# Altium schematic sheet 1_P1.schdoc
size 307 x 218 mm; Symbol: Drawing-Symbol_A4; Device: Drawing-Symbol_A4; Company: 嘉立创EDA; Version: V1.0; Page Size: A4; @Project Name: HDMI2CSI; @Page Count: 1; @Update Date: 2025-08-23; @Create Date: 2025-08-11; @Schematic Name: HDMI2CSI2; @Page No: 1; @Page Name: P1; @Create Time: 10:16:40; @Update Time: 00:30:52; Width: 1170; Height: 825; Region Start: 1; X Region Count: 6; Y Region Count: 4; Blade Width: 10; Title Block Position: 3; @Board Name: HDMI_2_CSI2
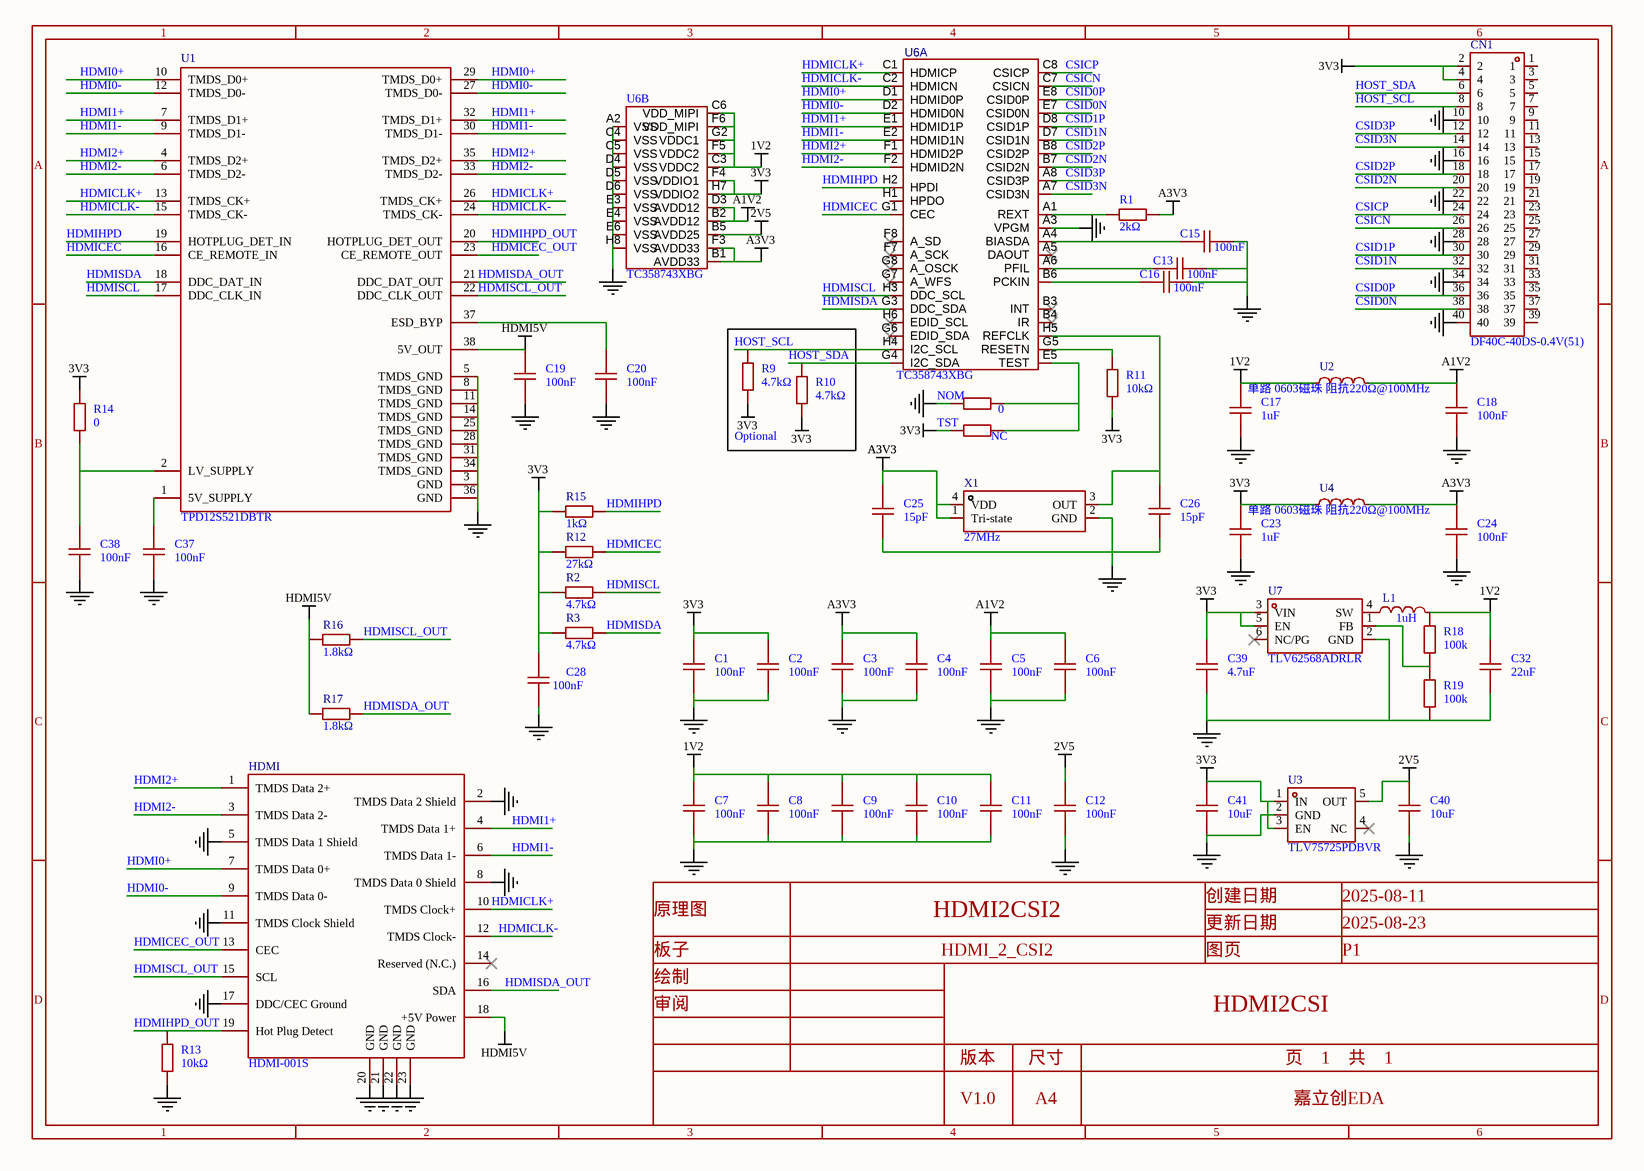
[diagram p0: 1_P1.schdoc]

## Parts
C1  100nF  [C0603]
C2  100nF  [C0603]
C3  100nF  [C0603]
C4  100nF  [C0603]
C5  100nF  [C0603]
C6  100nF  [C0603]
C7  100nF  [C0603]
C8  100nF  [C0603]
C9  100nF  [C0603]
C10  100nF  [C0603]
C11  100nF  [C0603]
C12  100nF  [C0603]
C13  100nF  [C0603]
C15  100nF  [C0603]
C16  100nF  [C0603]
C17  1uF  [C0603]
C18  100nF  [C0603]
C19  100nF  [C0603]
C20  100nF  [C0603]
C23  1uF  [C0603]
C24  100nF  [C0603]
C25  15pF  [C0603]
C26  15pF  [C0603]
C28  100nF  [C0603]
C32  22uF  [C0805]
C37  100nF  [C0603]
C38  100nF  [C0603]
C39  4.7uF  [C0603]
C40  10uF  [C0603]
C41  10uF  [C0603]
CN1  DF40C-40DS-0.4V(51)  [CONN-SMD_DF40C-40DS-0.4V51]
HDMI  HDMI-001S  [HDMI-SMD_HDMI-001S]
L1  1uH  [IND-SMD_L2.5-W2.0_WPN252012H]
NOM  0  [R0603]
R1  2kΩ  [R0603]
R2  4.7kΩ  [R0603]
R3  4.7kΩ  [R0603]
R9  4.7kΩ  [R0603]
R10  4.7kΩ  [R0603]
R11  10kΩ  [R0603]
R12  27kΩ  [R0603]
R13  10kΩ  [R0603]
R14  0  [R0603]
R15  1kΩ  [R0603]
R16  1.8kΩ  [R0603]
R17  1.8kΩ  [R0603]
R18  100k  [R0603]
R19  100k  [R0603]
TST  NC  [R0603]
U1  TPD12S521DBTR  [TSSOP-38_L9.7-W4.4-P0.50-LS6.4-BL]
U2  LCSC Part Name: 单路 0603磁珠 阻抗220Ω@100MHz  [L0603]  (hidden comment: BLM18EG221SN1D)
U3  TLV75725PDBVR  [SOT-23-5_L2.9-W1.6-P0.95-LS2.8-BR]
U4  LCSC Part Name: 单路 0603磁珠 阻抗220Ω@100MHz  [L0603]  (hidden comment: BLM18EG221SN1D)
U6  TC358743XBG  [BGA-64_L6.0-W6.0-W8-R8-P0.65-D0.40-TL]  (parts A,B of 2)
U7  TLV62568ADRLR  [SOT-563_L1.6-W1.2-P0.50-LS1.6-BL]
X1  27MHz  [OSC-SMD_4P-L3.2-W2.5-BL]

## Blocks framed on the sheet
Optional: R9 R10

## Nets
1V2: C7.2 C8.2 C9.2 C10.2 C11.2 C17.2 C32.2 L1.2 R18.2 U2.1 U6.C3(VDDC2) U6.C6(VDD_MIPI) U6.F5(VDDC2) U6.F6(VDD_MIPI) U6.G2(VDDC1)
2V5: C12.2 C40.2 U3.5(OUT) U6.B5(AVDD25)
3V3: C1.2 C2.2 C23.2 C28.2 C39.2 C41.2 CN1.2 CN1.4 R2.1 R3.1 R9.1 R10.1 R11.1 R12.1 R14.2 R15.1 TST.1 U3.1(IN) U3.3(EN) U4.1 U6.F4(VDDIO1) U6.H7(VDDIO2) U7.3(VIN) U7.5(EN)
A1V2: C5.2 C6.2 C18.2 U2.2 U6.B2(AVDD12) U6.D3(AVDD12)
A3V3: C3.2 C4.2 C24.2 C25.2 R1.2 U4.2 U6.B1(AVDD33) U6.F3(AVDD33) X1.1(Tri-state) X1.4(VDD)
GND: C1.1 C2.1 C3.1 C4.1 C5.1 C6.1 C7.1 C8.1 C9.1 C10.1 C11.1 C12.1 C13.2 C15.2 C16.2 C17.1 C18.1 C19.1 C20.1 C23.1 C24.1 C25.1 C26.1 C28.1 C32.1 C37.1 C38.1 C39.1 C40.1 C41.1 CN1.10 CN1.16 CN1.22 CN1.28 CN1.34 CN1.40 HDMI.2(TMDS_Data_2_Shield) HDMI.5(TMDS_Data_1_Shield) HDMI.8(TMDS_Data_0_Shield) HDMI.11(TMDS_Clock_Shield) HDMI.17(DDC/CEC_Ground) HDMI.20(GND) HDMI.21(GND) HDMI.22(GND) HDMI.23(GND) NOM.2 R13.1 R19.1 U1.3(GND) U1.5(TMDS_GND) U1.8(TMDS_GND) U1.11(TMDS_GND) U1.14(TMDS_GND) U1.25(TMDS_GND) U1.28(TMDS_GND) U1.31(TMDS_GND) U1.34(TMDS_GND) U1.36(GND) U3.2(GND) U6.A2(VSS) U6.A3(VPGM) U6.C4(VSS) U6.C5(VSS) U6.D4(VSS) U6.D5(VSS) U6.D6(VSS) U6.E3(VSS) U6.E4(VSS) U6.E6(VSS) U6.H8(VSS) U7.2(GND) X1.2(GND)
HDMI5V: C19.2 HDMI.18(+5V_Power) R16.1 R17.1 U1.38(5V_OUT)
CSICN: CN1.26 U6.C7(CSICN)
CSICP: CN1.24 U6.C8(CSICP)
CSID0N: CN1.38 U6.E7(CSID0N)
CSID0P: CN1.36 U6.E8(CSID0P)
CSID1N: CN1.32 U6.D7(CSID1N)
CSID1P: CN1.30 U6.D8(CSID1P)
CSID2N: CN1.20 U6.B7(CSID2N)
CSID2P: CN1.18 U6.B8(CSID2P)
CSID3N: CN1.14 U6.A7(CSID3N)
CSID3P: CN1.12 U6.A8(CSID3P)
HDMI0+: HDMI.7(TMDS_Data_0+) U1.10(TMDS_D0+) U1.29(TMDS_D0+) U6.D1(HDMID0P)
HDMI0-: HDMI.9(TMDS_Data_0-) U1.12(TMDS_D0-) U1.27(TMDS_D0-) U6.D2(HDMID0N)
HDMI1+: HDMI.4(TMDS_Data_1+) U1.7(TMDS_D1+) U1.32(TMDS_D1+) U6.E1(HDMID1P)
HDMI1-: HDMI.6(TMDS_Data_1-) U1.9(TMDS_D1-) U1.30(TMDS_D1-) U6.E2(HDMID1N)
HDMI2+: HDMI.1(TMDS_Data_2+) U1.4(TMDS_D2+) U1.35(TMDS_D2+) U6.F1(HDMID2P)
HDMI2-: HDMI.3(TMDS_Data_2-) U1.6(TMDS_D2-) U1.33(TMDS_D2-) U6.F2(HDMID2N)
HDMICEC: R12.2 U1.16(CE_REMOTE_IN) U6.G1(CEC)
HDMICEC_OUT: HDMI.13(CEC) U1.23(CE_REMOTE_OUT)
HDMICLK+: HDMI.10(TMDS_Clock+) U1.13(TMDS_CK+) U1.26(TMDS_CK+) U6.C1(HDMICP)
HDMICLK-: HDMI.12(TMDS_Clock-) U1.15(TMDS_CK-) U1.24(TMDS_CK-) U6.C2(HDMICN)
HDMIHPD: R15.2 U1.19(HOTPLUG_DET_IN) U6.H2(HPDI)
HDMIHPD_OUT: HDMI.19(Hot_Plug_Detect) R13.2 U1.20(HOTPLUG_DET_OUT)
HDMISCL: R2.2 U1.17(DDC_CLK_IN) U6.H3(DDC_SCL)
HDMISCL_OUT: HDMI.15(SCL) R16.2 U1.22(DDC_CLK_OUT)
HDMISDA: R3.2 U1.18(DDC_DAT_IN) U6.G3(DDC_SDA)
HDMISDA_OUT: HDMI.16(SDA) R17.2 U1.21(DDC_DAT_OUT)
HOST_SCL: CN1.8 R9.2 U6.H4(I2C_SCL)
HOST_SDA: CN1.6 R10.2 U6.G4(I2C_SDA)
NetC13_1: C13.1 U6.A6(PFIL)
NetC15_1: C15.1 U6.A4(BIASDA)
NetC16_1: C16.1 U6.B6(PCKIN)
NetC20_2: C20.2 U1.37(ESD_BYP)
NetC26_2: C26.2 U6.H5(REFCLK) X1.3(OUT)
NetC37_2: C37.2 U1.1(5V_SUPPLY)
NetC38_2: C38.2 R14.1 U1.2(LV_SUPPLY)
NetL1_1: L1.1 U7.4(SW)
NetNOM_1: NOM.1 TST.2 U6.E5(TEST)
NetR1_1: R1.1 U6.A1(REXT)
NetR11_2: R11.2 U6.G5(RESETN)
NetR18_1: R18.1 R19.2 U7.1(FB)

Not connected (* = marked no-connect by the designer): CN1 1 3 5 7 9 11 13 15 17 19 21 23 25 27 29 31 33 35 37 39; HDMI 14(Reserved_(N.C.))*; U3 4(NC)*; U6 A5(DAOUT)* B3(INT)* B4(IR)* F7(A_SCK)* F8(A_SD)* G6(EDID_SDA)* G7(A_WFS)* G8(A_OSCK)* H1(HPDO) H6(EDID_SCL)*; U7 6(NC/PG)*

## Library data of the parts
C1-C13 C15 C16 C18-C20 C24 C25 C37 C38 = CGA0603X7R104K500JT: Manufacturer: HRE(芯声); Symbol: Capacitance; Add into BOM: yes; Tolerance: ±10%; Voltage Rating: 50V; Temperature Coefficient: X7R
C17 C23 C39-C41 = CL10A105KB8NNNC: Manufacturer: SAMSUNG(三星); Symbol: Capacitance; Add into BOM: yes; Tolerance: ±10%; Voltage Rated: 50V; Temperature Coefficient: X5R
C26 = CL10C150JB8NNNC: Manufacturer: SAMSUNG(三星); Symbol: Capacitance; Add into BOM: yes; Tolerance: ±5%; Voltage Rated: 50V; Temperature Coefficient: C0G
C28 = CGA0603X7R104K500JT: Manufacturer: HRE(芯声); Symbol: CL05B104KO5NNNC; Add into BOM: yes; Tolerance: ±10%; Voltage Rating: 50V; Temperature Coefficient: X7R
C32 = CL21A226MAQNNNE: Manufacturer: SAMSUNG(三星); Symbol: Capacitance; Add into BOM: yes; Tolerance: ±20%; Voltage Rated: 25V; Temperature Coefficient: X5R
CN1 = DF40C-40DS-0.4V(51): Manufacturer: HRS(广濑); Add into BOM: yes; Pitch: 0.4mm; Gender: 母; Current Rating (Max): 300mA
HDMI = HDMI-001S: Manufacturer: XUNPU(讯普); Add into BOM: yes; Connector Type: HDMI-A; Gender: 母
L1 = WPN252012H1R0MT: Manufacturer: Sunlord(顺络); Symbol: SDFL1608S100KTF; Add into BOM: yes; Tolerance: ±20%; Current Rating: 3A; Current - Saturation(Isat): 4.2A; DC Resistance(DCR): 54mΩ
NOM R11 R13 R14 TST = 0603WAF1002T5E: Manufacturer: UNI-ROYAL(厚声); Symbol: 电阻; Add into BOM: yes; Tolerance: ±1%; Power(Watts): 100mW; Voltage-Supply(Max): 75V; Temperature Coefficient: ±100ppm/℃
R1 = 0603WAF2001T5E: Manufacturer: UNI-ROYAL(厚声); Symbol: 电阻; Add into BOM: yes; Tolerance: ±1%; Power(Watts): 100mW; Voltage-Supply(Max): 75V; Temperature Coefficient: ±100ppm/℃
R2 R3 R12 = 0603WAF4702T5E: Manufacturer: UNI-ROYAL(厚声); Symbol: 0402WGF4702TCE; Add into BOM: yes; Tolerance: ±1%; Power(Watts): 100mW; Voltage-Supply(Max): 75V; Temperature Coefficient: ±100ppm/℃
R9 R10 = 0603WAF4701T5E: Manufacturer: UNI-ROYAL(厚声); Symbol: 电阻; Add into BOM: yes; Tolerance: ±1%; Power(Watts): 100mW; Overload Voltage (Max): 75V; Temperature Coefficient: ±100ppm/℃
R15 = 0603WAF1003T5E: Manufacturer: UNI-ROYAL(厚声); Symbol: 0402WGF4702TCE; Add into BOM: yes; Tolerance: ±1%; Power(Watts): 100mW; Overload Voltage (Max): 75V; Temperature Coefficient: ±100ppm/℃
R16 R17 = M55342H12B1E70PT5: Manufacturer: VISHAY(威世); Symbol: 0402WGF4702TCE; Add into BOM: yes; Tolerance: ±1%; Power(Watts): 100mW; Temperature Coefficient: ±50ppm/℃
R18 R19 = Res_0603: Symbol: 电阻; Convert to PCB: yes
U1 = TPD12S521DBTR: Manufacturer: TI(德州仪器); Add into BOM: yes; Interface: HDMI; Voltage - Supply: 5V~5.5V
U2 U4 = BLM18EG221SN1D: Manufacturer: muRata(村田); Symbol: BLM18PG121SN1D_C14709; Add into BOM: yes; Impedance @ Frequency: 220Ω@100MHz; Tolerance: ±25%; DC Resistance: 50mΩ; Current Rating: 2A; Circuits: 1
U3 = TLV75725PDBVR: Manufacturer: TI(德州仪器); Add into BOM: yes; Output Type: 固定; Maximum Input Voltage: 5.5V; Output Voltage: 2.5V; Output Current: 1A; Dropout Voltage: 650mV@(1A); Output Polarity: 正极; Number of Outputs: 1
U6 = TC358743XBG: Add into BOM: yes
U7 = TLV62568ADRLR: Manufacturer: TI(德州仪器); Add into BOM: yes; Function: 降压型; Output Type: 可调; Voltage - Supply: 2.5V~5.5V; Output Voltage: 600mV~5.5V; Output Current: 1A; Frequency - Switching: 1.5MHz; Synchronous Rectifier: 是; Number of Outputs: 1; Topology: 降压式; Switch tube (built-in/external): 内置
X1 = OT2EL4C4JI-111OLP-27M: Manufacturer: YXC(扬兴晶振); Add into BOM: yes; Normal temperature Frequency Tolerance: ±10ppm; Output Type: CMOS; Voltage - Supply: 1.8V~3.3V; Frequency Stability: ±20ppm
